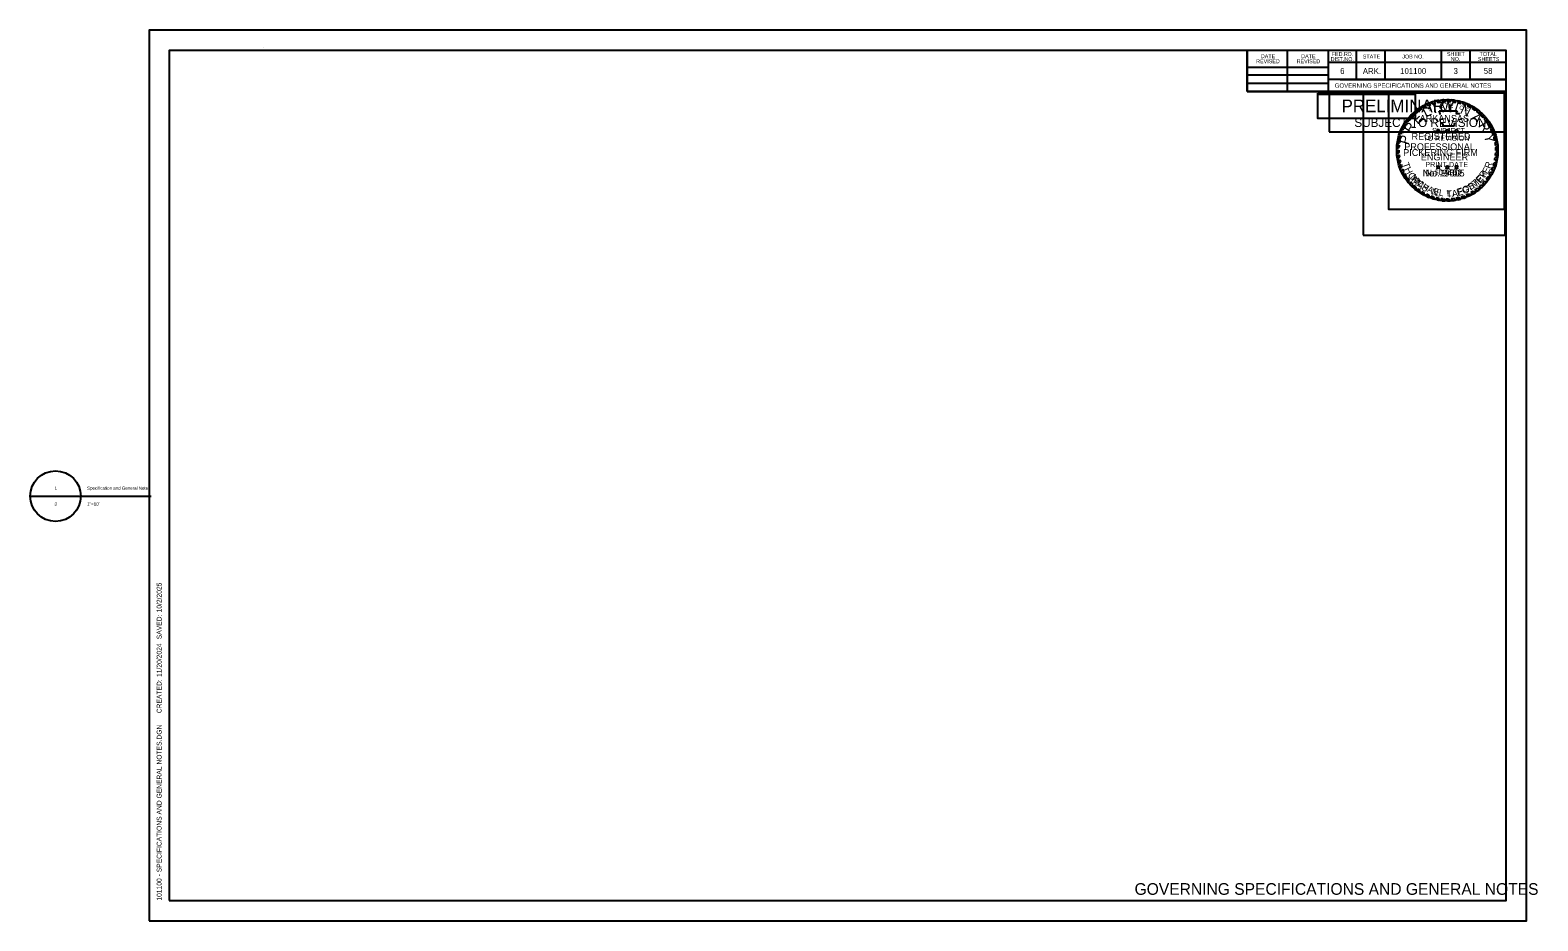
# Model space of a CAD drawing. Extents: x -0.12 to 1.43, y 0 to 0.92.
import ezdxf

# ---------------------------------------------------------------- set-up
doc = ezdxf.new("R2010")
doc.units = 0
for name, color, linetype in [('Default', 7, 'Continuous'), ('DSN_DRFT_Guideline-No-Plot', 7, 'Continuous'), ('SHET_Annotations', 7, 'Continuous'), ('SHET_Border-Lines', 7, 'Continuous'), ('SHET_Border-Text', 7, 'Continuous'), ('SHET_Stamp-Prelim', 7, 'Continuous'), ('SHET_Stamp-Seal', 7, 'Continuous'), ('STAMP_PE DIG SIG', 7, 'Continuous'), ('STAMP_PE_BACKGROUND', 7, 'Continuous'), ('STAMP_PE_FOSTER', 7, 'Continuous'), ('STAMP_PE_SEAL-INFO', 7, 'Continuous'), ('STAMP_PE_TAEGTMEYER', 7, 'Continuous'), ('STAMP_PRELIMINARY', 7, 'Continuous')]:
    doc.layers.add(name, color=color, linetype=linetype)

msp = doc.modelspace()

# ---------------------------------------------------------------- linework, layer by layer
at = {"layer": 'Default'}
for p, q in [((-0.1223, 0.4371), (-0.0702, 0.4371)), ((-0.096, 0.4371), (0.0023, 0.4371))]:
    msp.add_line(p, q, dxfattribs=at)
msp.add_circle((-0.0962, 0.4371), 0.026, dxfattribs=at)
at = {"layer": 'DSN_DRFT_Guideline-No-Plot'}
msp.add_lwpolyline([(0, 0), (1.4167, 0), (1.4167, 0.9167), (0, 0.9167)], close=True, dxfattribs=at)
at = {"layer": 'SHET_Border-Lines'}
for p, q in [((0.1176, 0.8988), (0.1176, 0.8988)), ((0.1176, 0.8988), (0.1176, 0.8988)), ((1.1296, 0.8534), (1.1296, 0.8958)), ((1.1711, 0.8534), (1.1711, 0.8958)), ((1.2127, 0.8958), (1.2127, 0.8534)), ((1.2417, 0.8958), (1.2417, 0.866)), ((1.2712, 0.8958), (1.2712, 0.866)), ((1.3289, 0.8958), (1.3289, 0.866)), ((1.3584, 0.8958), (1.3584, 0.866)), ((1.1296, 0.8786), (1.2127, 0.8786)), ((1.1296, 0.8706), (1.2127, 0.8706)), ((1.3958, 0.8832), (1.2127, 0.8832)), ((1.3958, 0.8833), (1.3958, 0.8833)), ((1.1296, 0.8622), (1.2127, 0.8622)), ((1.3958, 0.8534), (1.1296, 0.8534)), ((1.3958, 0.866), (1.2127, 0.866)), ((1.2252, 0.866), (1.3958, 0.866))]:
    msp.add_line(p, q, dxfattribs=at)
for points in [[(0.0208, 0.0208), (1.3958, 0.0208), (1.3958, 0.8958), (0.0208, 0.8958)], [(1.1296, 0.8534), (1.3958, 0.8534), (1.3958, 0.8958), (1.1296, 0.8958)]]:
    msp.add_lwpolyline(points, close=True, dxfattribs=at)
at = {"layer": 'SHET_Stamp-Prelim'}
msp.add_lwpolyline([(1.2137, 0.8119), (1.3948, 0.8119), (1.3948, 0.8524), (1.2137, 0.8524)], close=True, dxfattribs=at)
at = {"layer": 'SHET_Stamp-Seal'}
msp.add_line((1.3219, 0.7895), (1.3219, 0.7895), dxfattribs=at)
msp.add_lwpolyline([(1.249, 0.7057), (1.3948, 0.7057), (1.3948, 0.8524), (1.249, 0.8524)], close=True, dxfattribs=at)
at = {"layer": 'STAMP_PE DIG SIG'}
msp.add_lwpolyline([(1.2022, 0.8508), (1.3022, 0.8508), (1.3022, 0.8258), (1.2022, 0.8258)], close=True, dxfattribs=at)
at = {"layer": 'STAMP_PE_BACKGROUND'}
for points in [[(1.2022, 0.8517), (1.3022, 0.8517), (1.3022, 0.8258), (1.2022, 0.8258)], [(1.3942, 0.8517), (1.275, 0.8517), (1.275, 0.7325), (1.3942, 0.7325)]]:
    msp.add_lwpolyline(points, close=True, dxfattribs=at)
at = {"layer": 'STAMP_PE_SEAL-INFO'}
for p, q in [((1.3087, 0.8377), (1.3112, 0.8365)), ((1.3112, 0.8391), (1.3138, 0.8378)), ((1.3137, 0.8403), (1.3158, 0.8387)), ((1.3165, 0.8415), (1.3181, 0.8397)), ((1.3184, 0.8422), (1.3206, 0.8405)), ((1.3217, 0.8432), (1.3233, 0.8413)), ((1.3239, 0.8438), (1.3259, 0.8418)), ((1.3266, 0.8443), (1.3283, 0.8422)), ((1.3295, 0.8447), (1.331, 0.8426)), ((1.3336, 0.8427), (1.3318, 0.8449)), ((1.3364, 0.8428), (1.3348, 0.845)), ((1.3389, 0.8426), (1.3375, 0.845)), ((1.3417, 0.8424), (1.3401, 0.8448)), ((1.3441, 0.842), (1.3427, 0.8445)), ((1.3473, 0.8413), (1.3463, 0.8439)), ((1.3495, 0.8407), (1.3486, 0.8433)), ((1.352, 0.8399), (1.3512, 0.8426)), ((1.3544, 0.839), (1.3536, 0.8418)), ((1.357, 0.8379), (1.3564, 0.8406)), ((1.3594, 0.8366), (1.359, 0.8394)), ((1.3616, 0.8353), (1.3614, 0.8381)), ((1.293, 0.8232), (1.2959, 0.8232)), ((1.2946, 0.8253), (1.2977, 0.8254)), ((1.2965, 0.8276), (1.2994, 0.8274)), ((1.2983, 0.8295), (1.3014, 0.8293)), ((1.3002, 0.8313), (1.3028, 0.8306)), ((1.3021, 0.833), (1.3051, 0.8325)), ((1.3042, 0.8348), (1.3068, 0.8337)), ((1.3066, 0.8363), (1.309, 0.8352)), ((1.3269, 0.8337), (1.3456, 0.8337)), ((1.3276, 0.832), (1.3269, 0.8337)), ((1.3281, 0.8303), (1.3276, 0.832)), ((1.3282, 0.8297), (1.3281, 0.8303)), ((1.3456, 0.8337), (1.3443, 0.831)), ((1.3443, 0.831), (1.3478, 0.831)), ((1.3478, 0.831), (1.347, 0.8297)), ((1.364, 0.8337), (1.3639, 0.8366)), ((1.366, 0.8322), (1.3662, 0.8349)), ((1.3685, 0.8301), (1.3687, 0.8331)), ((1.3703, 0.8285), (1.3707, 0.8313)), ((1.3723, 0.8264), (1.3727, 0.8294)), ((1.3738, 0.8247), (1.3746, 0.8273)), ((1.3756, 0.8223), (1.3764, 0.8251)), ((1.3769, 0.8206), (1.3779, 0.8232)), ((1.2853, 0.8071), (1.2879, 0.808)), ((1.2862, 0.8099), (1.2889, 0.8106)), ((1.287, 0.8121), (1.2898, 0.8129)), ((1.288, 0.8145), (1.2908, 0.8151)), ((1.2891, 0.8167), (1.2918, 0.8171)), ((1.2904, 0.8191), (1.2931, 0.8192)), ((1.2917, 0.8213), (1.2946, 0.8215)), ((1.3252, 0.8129), (1.3241, 0.8137)), ((1.3241, 0.8137), (1.3255, 0.8137)), ((1.3248, 0.8116), (1.3252, 0.8129)), ((1.3259, 0.8124), (1.3248, 0.8116)), ((1.3255, 0.8137), (1.3259, 0.815)), ((1.3259, 0.815), (1.3264, 0.8137)), ((1.327, 0.8116), (1.3259, 0.8124)), ((1.3264, 0.8137), (1.3277, 0.8137)), ((1.3277, 0.8137), (1.3266, 0.8129)), ((1.3266, 0.8129), (1.327, 0.8116)), ((1.3293, 0.8201), (1.3291, 0.8213)), ((1.331, 0.8201), (1.3293, 0.8201)), ((1.331, 0.8177), (1.331, 0.8201)), ((1.3423, 0.8177), (1.331, 0.8177)), ((1.3347, 0.8129), (1.3336, 0.8137)), ((1.3336, 0.8137), (1.335, 0.8137)), ((1.3343, 0.8116), (1.3347, 0.8129)), ((1.3354, 0.8124), (1.3343, 0.8116)), ((1.335, 0.8137), (1.3354, 0.815)), ((1.3354, 0.815), (1.3358, 0.8137)), ((1.3365, 0.8116), (1.3354, 0.8124)), ((1.3358, 0.8137), (1.3372, 0.8137)), ((1.3372, 0.8137), (1.3361, 0.8129)), ((1.3361, 0.8129), (1.3365, 0.8116)), ((1.3424, 0.8196), (1.3423, 0.8177)), ((1.3429, 0.8213), (1.3424, 0.8196)), ((1.3442, 0.8129), (1.3431, 0.8137)), ((1.3431, 0.8137), (1.3445, 0.8137)), ((1.3438, 0.8116), (1.3442, 0.8129)), ((1.3449, 0.8124), (1.3438, 0.8116)), ((1.3445, 0.8137), (1.3449, 0.815)), ((1.3449, 0.815), (1.3453, 0.8137)), ((1.346, 0.8116), (1.3449, 0.8124)), ((1.3453, 0.8137), (1.3467, 0.8137)), ((1.3467, 0.8137), (1.3456, 0.8129)), ((1.3456, 0.8129), (1.346, 0.8116)), ((1.3786, 0.8178), (1.3796, 0.8205)), ((1.3797, 0.8157), (1.381, 0.8182)), ((1.381, 0.813), (1.3823, 0.8157)), ((1.3818, 0.8112), (1.3832, 0.8136)), ((1.3829, 0.8081), (1.3844, 0.8107)), ((1.3835, 0.8061), (1.3851, 0.8086)), ((1.2857, 0.796), (1.2834, 0.7946)), ((1.2856, 0.7933), (1.2834, 0.7914)), ((1.2859, 0.7984), (1.2835, 0.7968)), ((1.2857, 0.791), (1.2835, 0.7892)), ((1.2862, 0.8008), (1.2838, 0.7996)), ((1.2867, 0.8034), (1.2841, 0.802)), ((1.2847, 0.8048), (1.2873, 0.8059)), ((1.3842, 0.8029), (1.386, 0.8054)), ((1.3846, 0.8008), (1.3866, 0.8028)), ((1.385, 0.798), (1.387, 0.7998)), ((1.3851, 0.7956), (1.3873, 0.7973)), ((1.3852, 0.7927), (1.3875, 0.7945)), ((1.3852, 0.7905), (1.3875, 0.792)), ((1.2858, 0.7882), (1.2838, 0.7862)), ((1.2861, 0.7858), (1.2842, 0.7837)), ((1.2866, 0.7833), (1.2847, 0.7812)), ((1.2871, 0.7809), (1.2854, 0.7786)), ((1.2878, 0.7784), (1.2861, 0.7761)), ((1.2886, 0.7761), (1.287, 0.7738)), ((1.3252, 0.7754), (1.3241, 0.7763)), ((1.3241, 0.7763), (1.3255, 0.7763)), ((1.3248, 0.7741), (1.3252, 0.7754)), ((1.3255, 0.7763), (1.3259, 0.7776)), ((1.3259, 0.7776), (1.3264, 0.7763)), ((1.3264, 0.7763), (1.3277, 0.7763)), ((1.3277, 0.7763), (1.3266, 0.7754)), ((1.3266, 0.7754), (1.327, 0.7741)), ((1.3347, 0.7754), (1.3336, 0.7763)), ((1.3336, 0.7763), (1.335, 0.7763)), ((1.3343, 0.7741), (1.3347, 0.7754)), ((1.335, 0.7763), (1.3354, 0.7776)), ((1.3354, 0.7776), (1.3358, 0.7763)), ((1.3358, 0.7763), (1.3372, 0.7763)), ((1.3372, 0.7763), (1.3361, 0.7754)), ((1.3361, 0.7754), (1.3365, 0.7741)), ((1.3442, 0.7754), (1.3431, 0.7763)), ((1.3431, 0.7763), (1.3445, 0.7763)), ((1.3438, 0.7741), (1.3442, 0.7754)), ((1.3445, 0.7763), (1.3449, 0.7776)), ((1.3449, 0.7776), (1.3453, 0.7763)), ((1.3453, 0.7763), (1.3467, 0.7763)), ((1.3467, 0.7763), (1.3456, 0.7754)), ((1.3456, 0.7754), (1.346, 0.7741)), ((1.382, 0.7753), (1.3847, 0.776)), ((1.3827, 0.7774), (1.3855, 0.7785)), ((1.3835, 0.7802), (1.3862, 0.7813)), ((1.3841, 0.7827), (1.3867, 0.7838)), ((1.3846, 0.7855), (1.3871, 0.7867)), ((1.3849, 0.7876), (1.3874, 0.7891)), ((1.2895, 0.7737), (1.288, 0.7713)), ((1.2905, 0.7715), (1.2892, 0.769)), ((1.2918, 0.769), (1.2907, 0.7662)), ((1.2931, 0.7667), (1.2921, 0.7641)), ((1.2942, 0.765), (1.2936, 0.7619)), ((1.2958, 0.7628), (1.2952, 0.7598)), ((1.2975, 0.7607), (1.297, 0.7578)), ((1.3259, 0.7749), (1.3248, 0.7741)), ((1.327, 0.7741), (1.3259, 0.7749)), ((1.3354, 0.7749), (1.3343, 0.7741)), ((1.3365, 0.7741), (1.3354, 0.7749)), ((1.3449, 0.7749), (1.3438, 0.7741)), ((1.346, 0.7741), (1.3449, 0.7749)), ((1.3738, 0.7612), (1.3763, 0.7608)), ((1.3755, 0.7634), (1.3783, 0.7634)), ((1.3774, 0.7662), (1.3801, 0.7661)), ((1.3783, 0.7677), (1.3811, 0.768)), ((1.3799, 0.7705), (1.3826, 0.7709)), ((1.3808, 0.7724), (1.3835, 0.7729)), ((1.2992, 0.7588), (1.2988, 0.7559)), ((1.301, 0.757), (1.3008, 0.754)), ((1.3029, 0.7552), (1.3029, 0.7523)), ((1.3049, 0.7536), (1.305, 0.7507)), ((1.3068, 0.7522), (1.307, 0.7493)), ((1.3092, 0.7506), (1.3095, 0.7478)), ((1.3111, 0.7495), (1.3117, 0.7466)), ((1.3138, 0.7481), (1.3147, 0.7452)), ((1.3159, 0.7471), (1.3169, 0.7443)), ((1.3187, 0.7461), (1.3198, 0.7433)), ((1.321, 0.7453), (1.3222, 0.7426)), ((1.3238, 0.7445), (1.325, 0.7419)), ((1.3471, 0.7446), (1.3492, 0.7427)), ((1.3497, 0.7453), (1.352, 0.7436)), ((1.3524, 0.7462), (1.3549, 0.7447)), ((1.3548, 0.7471), (1.3571, 0.7456)), ((1.3573, 0.7483), (1.36, 0.7471)), ((1.3596, 0.7494), (1.3619, 0.7481)), ((1.3619, 0.7508), (1.3644, 0.7497)), ((1.3639, 0.7521), (1.3663, 0.751)), ((1.3664, 0.754), (1.369, 0.7532)), ((1.3679, 0.7553), (1.3706, 0.7545)), ((1.3702, 0.7573), (1.3727, 0.7566)), ((1.3716, 0.7588), (1.3743, 0.7583)), ((1.326, 0.7441), (1.3274, 0.7415)), ((1.3288, 0.7436), (1.3302, 0.7411)), ((1.3313, 0.7433), (1.3328, 0.7409)), ((1.334, 0.7432), (1.3356, 0.7409)), ((1.3365, 0.7432), (1.3384, 0.741)), ((1.3394, 0.7433), (1.3412, 0.7412)), ((1.3419, 0.7436), (1.344, 0.7416)), ((1.3444, 0.744), (1.3465, 0.7421))]:
    msp.add_line(p, q, dxfattribs=at)
for radius, start, end in [(0.0521, 117.6544, 120.8099), (0.0498, 115.6869, 119.1583), (0.0521, 111.3124, 114.7026), (0.0498, 110.3086, 113.1659), (0.0521, 105.2339, 109.0352), (0.0498, 104.0352, 107.3615), (0.0521, 99.7525, 102.7765), (0.0498, 98.258, 101.0329), (0.0521, 93.9381, 96.5517), (0.0498, 92.1102, 95.0367), (0.0521, 87.7298, 90.6707), (0.0498, 85.9628, 88.9097), (0.0521, 81.9732, 84.8236), (0.0498, 79.9264, 82.696), (0.0521, 75.3125, 77.9426), (0.0498, 73.5575, 76.2314), (0.0521, 69.6061, 72.3058), (0.0498, 67.6248, 70.504), (0.0521, 63.1329, 66.2704), (0.0498, 61.1558, 64.3784), (0.0521, 56.9003, 60.0942), (0.0521, 141.6056, 144.4486), (0.0498, 139.301, 142.5873), (0.0521, 135.4021, 138.3031), (0.0498, 133.1331, 136.2562), (0.0521, 129.7326, 132.5376), (0.0498, 127.5297, 130.9683), (0.0521, 123.6199, 126.5906), (0.0498, 121.9746, 125.11), (0.0498, 54.9238, 58.2702), (0.0498, 48.3016, 52.0395), (0.0521, 50.3492, 53.7159), (0.0498, 42.2212, 45.5512), (0.0521, 44.3405, 47.3929), (0.0498, 36.135, 39.5311), (0.0521, 38.1247, 41.2316), (0.0521, 31.9614, 35.4294), (0.0521, 164.3068, 166.894), (0.0521, 158.4077, 161.0701), (0.0498, 162.4331, 165.0013), (0.0521, 152.864, 155.5189), (0.0498, 156.3402, 159.2319), (0.0521, 147.0072, 149.899), (0.0498, 151.0315, 153.573), (0.0498, 145.0197, 148.2104), (0.0498, 29.9032, 33.6645), (0.0498, 23.7732, 27.2211), (0.0521, 25.9391, 29.0125), (0.0498, 17.6802, 21.4251), (0.0521, 19.9538, 23.3141), (0.0521, 13.8421, 17.4447), (0.0521, 175.7409, 178.2066), (0.0521, 181.7251, 184.1626), (0.0521, 170.0003, 172.6878), (0.0498, 179.6454, 182.2633), (0.0498, 173.73, 176.4734), (0.0498, 167.9048, 170.9039), (0.0498, 11.5444, 15.2364), (0.0498, 5.7599, 9.0606), (0.0498, 359.7329, 3.0639), (0.0521, 7.5852, 10.8621), (0.0521, 1.7215, 4.7268), (0.0521, 355.7156, 358.9569), (0.0521, 187.4204, 190.1927), (0.0521, 193.0369, 195.9973), (0.0498, 185.4539, 188.234), (0.0521, 198.8967, 201.6281), (0.0498, 191.2274, 193.9858), (0.0498, 196.9675, 199.8353), (0.0498, 341.777, 345.0925), (0.0521, 337.3837, 340.9933), (0.0498, 348.0778, 351.3435), (0.0498, 353.8632, 357.1274), (0.0521, 343.8925, 347.035), (0.0521, 349.8305, 353.0885), (0.0521, 204.5479, 207.4328), (0.0498, 202.7761, 205.4791), (0.0521, 210.8636, 213.6571), (0.0498, 208.7883, 211.7934), (0.0521, 216.6115, 219.491), (0.0498, 214.1838, 217.2747), (0.0498, 220.3909, 223.3056), (0.0498, 316.6531, 320.3711), (0.0521, 318.2846, 321.8043), (0.0498, 323.5851, 327.4407), (0.0498, 329.5549, 333.2076), (0.0521, 325.4405, 328.9872), (0.0498, 335.6038, 339.1858), (0.0521, 331.4037, 334.9332), (0.0521, 222.48, 225.3801), (0.0521, 228.3665, 231.348), (0.0498, 226.2494, 229.2407), (0.0498, 232.229, 234.9336), (0.0521, 234.295, 236.9452), (0.0498, 238.2223, 240.8353), (0.0521, 240.1977, 242.8613), (0.0498, 244.3204, 246.9486), (0.0521, 246.576, 249.1558), (0.0498, 250.3491, 253.1216), (0.0498, 256.505, 259.1192), (0.0498, 280.3459, 283.5814), (0.0498, 286.6423, 289.9783), (0.0521, 288.5709, 291.9733), (0.0498, 292.8745, 296.1185), (0.0521, 294.6481, 298.2166), (0.0498, 299.0768, 302.1724), (0.0521, 300.621, 303.8703), (0.0498, 304.823, 308.5143), (0.0521, 306.3721, 310.208), (0.0498, 310.7744, 314.3161), (0.0521, 312.4518, 315.6633), (0.0521, 252.5967, 255.3252), (0.0521, 258.4433, 261.1398), (0.0498, 262.3783, 265.2012), (0.0521, 264.1978, 267.1009), (0.0498, 268.3215, 271.277), (0.0521, 270.2548, 273.3361), (0.0498, 274.6157, 277.4486), (0.0521, 276.4239, 279.4357), (0.0521, 282.3199, 285.3702)]:
    msp.add_arc((1.3354, 0.793), radius, start, end, dxfattribs=at)
at = {"layer": 'STAMP_PRELIMINARY'}
msp.add_circle((1.3354, 0.793), 0.0521, dxfattribs=at)

# ---------------------------------------------------------------- texts
at = {"layer": 'Default'}
for s, height, p in [('1', 0.00328, (-0.0971, 0.4437)), ('Specification and General Notes', 0.003281, (-0.0637, 0.4437)), ('3', 0.00328, (-0.0972, 0.4273)), ('1"=10\'', 0.00328, (-0.0637, 0.4273))]:
    msp.add_text(s, height=height, dxfattribs=at).set_placement(p)
at = {"layer": 'SHET_Annotations'}
for s, height, p in [('6', 0.006, (1.2252, 0.8716)), ('ARK.', 0.006, (1.2485, 0.8716)), ('101100', 0.006, (1.2869, 0.8716)), ('3', 0.006, (1.3418, 0.8716)), ('58', 0.006, (1.3729, 0.8717)), ('GOVERNING SPECIFICATIONS AND GENERAL NOTES', 0.0045, (1.2196, 0.8574)), ('GOVERNING SPECIFICATIONS AND GENERAL NOTES', 0.012, (1.0137, 0.0268))]:
    msp.add_text(s, height=height, dxfattribs=at).set_placement(p)
at = {"layer": 'SHET_Border-Text'}
for s, p in [('REVISED', (1.1388, 0.8826)), ('DATE', (1.1436, 0.8878)), ('REVISED', (1.1804, 0.8826)), ('DATE', (1.1851, 0.8878)), ('DIST.NO.', (1.2154, 0.8849)), ('FED.RD.', (1.2165, 0.8901)), ('STATE', (1.2485, 0.8875)), ('JOB NO.', (1.2891, 0.8875)), ('SHEET', (1.335, 0.8901)), ('NO.', (1.339, 0.8849)), ('SHEETS', (1.3668, 0.8849)), ('TOTAL', (1.3686, 0.8901))]:
    msp.add_text(s, height=0.004, dxfattribs=at).set_placement(p)
for s, p in [('10/2/2025', (0.0129, 0.3174)), ('  SAVED: ', (0.0129, 0.286)), ('11/20/2024', (0.0129, 0.251)), ('     CREATED: ', (0.0129, 0.2041)), ('101100 - SPECIFICATIONS AND GENERAL NOTES.DGN', (0.0129, 0.0208))]:
    msp.add_text(s, height=0.005, rotation=90, dxfattribs=at).set_placement(p)
at = {"layer": 'SHET_Stamp-Prelim'}
for s, height, p in [('PRELIMINARY', 0.013, (1.2266, 0.8322)), ('SUBJECT TO REVISION', 0.009, (1.2398, 0.817))]:
    msp.add_text(s, height=height, dxfattribs=at).set_placement(p)
at = {"layer": 'STAMP_PE_FOSTER'}
for s, rotation, p in [('M', 308.339, (1.297, 0.7652)), ('I', 314.1842, (1.3014, 0.7599)), ('C', 319.8733, (1.3034, 0.7579)), ('T', 39.4194, (1.3641, 0.7552)), ('E', 46.9613, (1.3689, 0.7594)), ('R', 54.5031, (1.373, 0.764)), ('H', 327.7235, (1.3086, 0.7538)), ('A', 335.7276, (1.3141, 0.7506)), ('E', 343.5779, (1.3204, 0.748)), ('L', 350.8115, (1.3263, 0.7464)), ('L', 1.2666, (1.3349, 0.7455)), ('.', 6.8035, (1.3408, 0.7459)), ('F', 15.8691, (1.3468, 0.7469)), ('O', 23.719, (1.3526, 0.7487)), ('S', 31.7234, (1.3588, 0.7517))]:
    msp.add_text(s, height=0.0067, rotation=rotation, dxfattribs=at).set_placement(p)
msp.add_text('No. 9402', height=0.00698, dxfattribs=at).set_placement((1.313, 0.7661))
at = {"layer": 'STAMP_PE_SEAL-INFO'}
for s, rotation, p in [('S', 23.5541, (1.3164, 0.8327)), ('T', 16.311, (1.3216, 0.8347)), ('A', 9.0679, (1.3269, 0.8361)), ('T', 1.8248, (1.3325, 0.8369)), ('E', 355.2002, (1.3375, 0.8369)), ('O', 342.2506, (1.3472, 0.8354)), ('F', 335.0075, (1.3526, 0.8335))]:
    msp.add_text(s, height=0.00436, rotation=rotation, dxfattribs=at).set_placement(p)
for s, height, p in [('ARKANSAS', 0.00698, (1.3069, 0.8223)), ('REGISTERED', 0.00698, (1.2986, 0.8038)), ('PROFESSIONAL', 0.006983, (1.2911, 0.7932)), ('ENGINEER', 0.00698, (1.3081, 0.7826))]:
    msp.add_text(s, height=height, dxfattribs=at).set_placement(p)
at = {"layer": 'STAMP_PE_TAEGTMEYER'}
for s, rotation, p in [('T', 289.646, (1.289, 0.7791)), ('H', 296.7339, (1.291, 0.7736)), ('E', 63.0984, (1.377, 0.768)), ('R', 69.57, (1.3798, 0.7735)), ('O', 303.7708, (1.2943, 0.7674)), ('M', 314.2033, (1.298, 0.7621)), ('A', 321.0594, (1.3034, 0.7567)), ('M', 39.3, (1.3633, 0.7533)), ('E', 46.8094, (1.3692, 0.7582)), ('Y', 53.9986, (1.3733, 0.7628)), ('S', 327.8239, (1.308, 0.7531)), ('N', 344.2727, (1.3186, 0.7474)), ('.', 350.6464, (1.3254, 0.7456)), ('T', 3.0061, (1.3347, 0.7445)), ('A', 8.9826, (1.3405, 0.7448)), ('E', 17.6836, (1.3463, 0.7457)), ('G', 23.3052, (1.3522, 0.7475)), ('T', 31.466, (1.3583, 0.7503))]:
    msp.add_text(s, height=0.00698, rotation=rotation, dxfattribs=at).set_placement(p)
msp.add_text('No. 19605', height=0.00698, dxfattribs=at).set_placement((1.3101, 0.7661))
at = {"layer": 'STAMP_PRELIMINARY'}
for s, rotation, p in [('I', 12.5248, (1.3217, 0.8309)), ('M', 3.1074, (1.3278, 0.8326)), ('I', 342.3164, (1.3416, 0.833)), ('N', 333.9382, (1.3478, 0.8315)), ('E', 42.3578, (1.3048, 0.8192)), ('L', 25.513, (1.3131, 0.8266)), ('A', 315.6579, (1.3591, 0.8257)), ('R', 301.3831, (1.3668, 0.8184)), ('P', 73.913, (1.2953, 0.7982)), ('R', 56.2292, (1.2984, 0.8095)), ('Y', 283.2593, (1.3729, 0.8084))]:
    msp.add_text(s, height=0.0101, rotation=rotation, dxfattribs=at).set_placement(p)
for s, height, p in [('TO REVISION', 0.005363, (1.3105, 0.8028)), ('SUBJECT', 0.00536, (1.3198, 0.8106)), ('PICKERING FIRM', 0.006983, (1.29, 0.7872)), ('PRINT DATE', 0.00536, (1.3128, 0.7757)), ('$DATE$', 0.00536, (1.3222, 0.768))]:
    msp.add_text(s, height=height, dxfattribs=at).set_placement(p)

doc.saveas('drawing.dxf')
